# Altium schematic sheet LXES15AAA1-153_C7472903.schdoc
size 127 x 101 mm
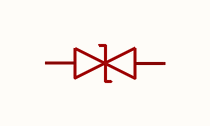
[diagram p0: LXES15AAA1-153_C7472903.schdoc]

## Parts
D?  lxes15aaa1-153_c7472903  [DFN1006-2L-BI]  (value not drawn)

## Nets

Not connected (* = marked no-connect by the designer): D? 1 2

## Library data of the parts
D? = lxes15aaa1-153_c7472903: 极性:双向;反向截止电压(Vrwm):5V;钳位电压:40V;峰值脉冲电流(Ipp):-;峰值脉冲功率(Ppp):-;击穿电压:-;; Manufacturer: TECH PUBLIC(台舟); AddInBom: yes; ModelId: 2bdbcca3b35b49c5a8ae725a08658930; ModelTransform: 40.1574,24.4094,0,0,0,0,0,0,0; Polarity: 双向; Reverse Stand-Off Voltage (Vrwm): 5V; Clamping Voltage: 40V; Reverse Leakage Current (Ir): 10nA; Number of Channels: 单路; level of protection: IEC 61000-4-2; Junction Capacitance: 0.05pF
